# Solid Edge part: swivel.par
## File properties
Title: Swivel
Author: Abhinav Rai
Template: normal.par
Last saved by: Cadcim
Revision: 12
Application: Solid Edge
Density: 0.0000078 kg/mm^3
Accuracy: 0.01
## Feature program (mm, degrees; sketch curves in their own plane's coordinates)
sketch for "unnamed RevolvedProtrusion 1" plane through (0, 0, -25.4) normal (0, 0, 1) x-axis (1, 0, 0)
revolve "unnamed RevolvedProtrusion 1" add finite 360 deg about sketch line (-85.0097, -12.7562) -> (-3.81, -12.7562)
sketch for "unnamed RevolvedProtrusion 2" plane through (0, -12.7, 0) normal (0, -1, 0) x-axis (1, 0, 0)
revolve "unnamed RevolvedProtrusion 2" add full turn 360 deg about sketch line (-44.45, 28.0428) -> (-44.45, -71.2043)
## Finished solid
Body 1: solid body, 14 faces, 13 edges, 0 vertices.
  Faces by surface: plane 8, cylinder 6
  Edges by curve: circle 12, intersection 1
Bounding box of the edges (mm): 81.200 x 25.456 x 81.280, from (-85.0097, -25.4562, -66.04) to (-3.81, 0, 15.24).
Cylindrical faces by radius (mm): R6.35 x4, R12.7 x2
Planar faces by outward normal: +x 2, +z 2, -x 2, -z 2
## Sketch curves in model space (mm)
line (-85.0097, -12.7562, -25.4) -> (-3.81, -12.7562, -25.4)
line (-85.0097, -19.1062, -25.4) -> (-85.0097, -12.7562, -25.4)
line (-85.0097, -19.1062, -25.4) -> (-69.7697, -19.1062, -25.4)
line (-69.7697, -19.1062, -25.4) -> (-69.7697, -25.4562, -25.4)
line (-69.7697, -25.4562, -25.4) -> (-19.05, -25.4562, -25.4)
line (-19.05, -25.4562, -25.4) -> (-19.05, -19.1062, -25.4)
line (-19.05, -19.1062, -25.4) -> (-3.81, -19.1062, -25.4)
line (-3.81, -19.1062, -25.4) -> (-3.81, -12.7562, -25.4)
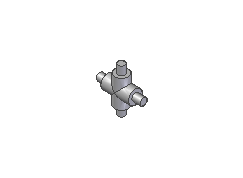
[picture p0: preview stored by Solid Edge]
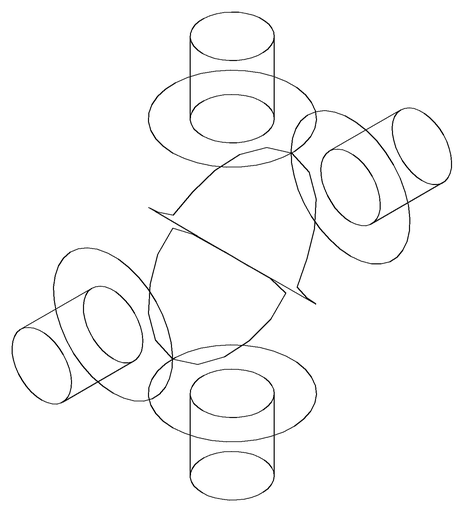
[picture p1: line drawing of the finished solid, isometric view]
